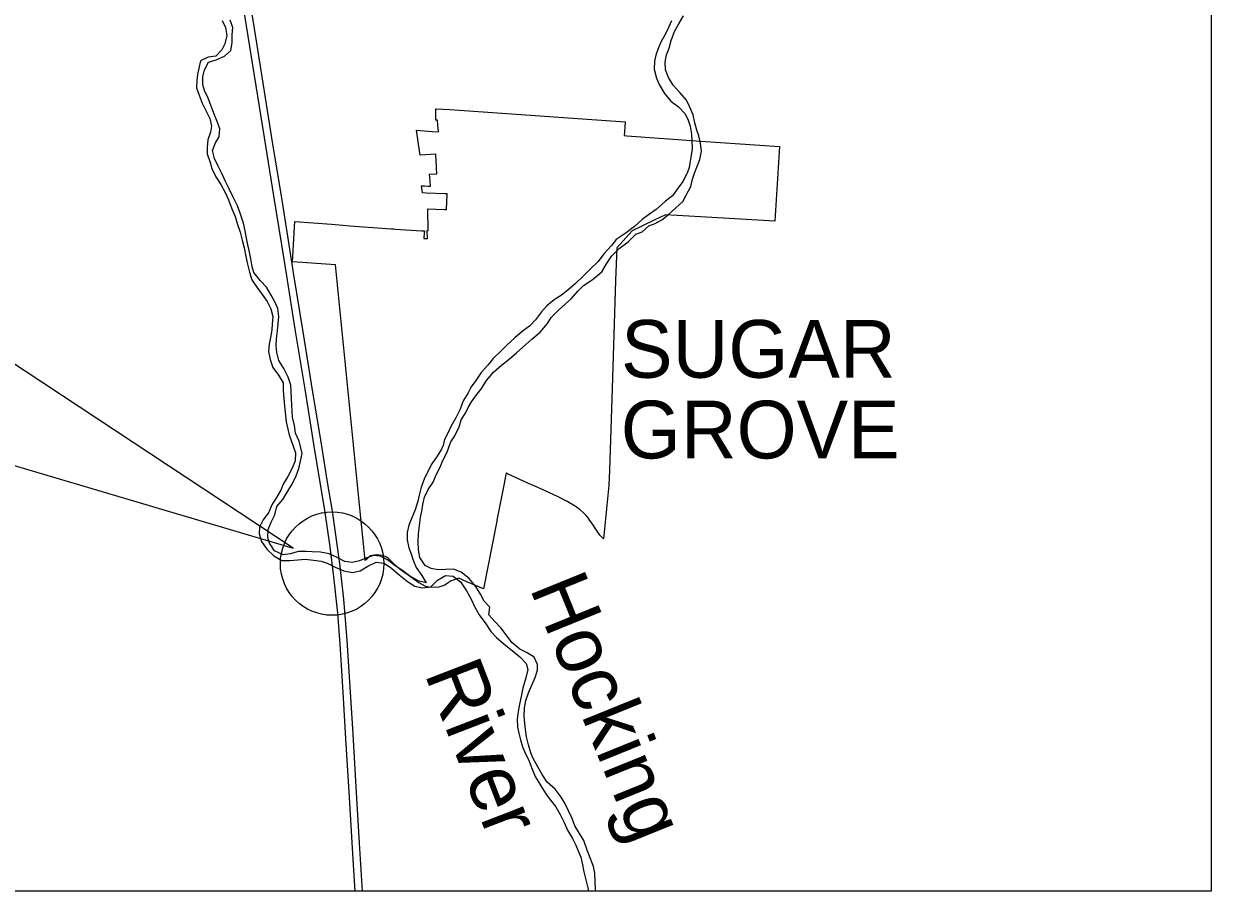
# Model space of a CAD drawing. Extents: x -51.9 to 34, y 0 to 23.3.
# Drawn here: x 9.235 to 12.658, y 11.236 to 13.737 of the extents above; entities that cross this region are included whole.
import ezdxf

# ---------------------------------------------------------------- set-up
doc = ezdxf.new("R2010")
doc.units = 0
for name, color, linetype in [('BR_P_Gen_Text', 7, 'Continuous'), ('Default', 7, 'Continuous'), ('GM_X_Corporation', 7, 'Continuous'), ('GM_X_Corporation_Text', 7, 'Continuous'), ('GM_X_Major_River', 7, 'Continuous'), ('GM_X_Major_River_Text', 7, 'Continuous'), ('GM_X_US_Route', 7, 'Continuous'), ('SH_Text', 7, 'Continuous')]:
    doc.layers.add(name, color=color, linetype=linetype)

msp = doc.modelspace()

# ---------------------------------------------------------------- linework, layer by layer
at = {"layer": 'BR_P_Gen_Text'}
msp.add_lwpolyline([(9.1878, 12.7694), (9.1878, 12.4691), (10.0115, 12.2252)], close=True, dxfattribs=at)
at = {"layer": 'Default'}
msp.add_circle((10.1237, 12.1807), 0.149, dxfattribs=at)
at = {"layer": 'GM_X_Corporation'}
msp.add_lwpolyline([(10.9674, 13.438), (10.966, 13.4149), (10.9733, 13.4144), (11.187, 13.3992), (11.414, 13.383), (11.3998, 13.1683), (11.1854, 13.1809), (11.1183, 13.1848), (11.0848, 13.1868), (11.0519, 13.1709), (10.9892, 13.1406), (10.9443, 13.0914), (10.9409, 12.9969), (10.9309, 12.6853), (10.9233, 12.4499), (10.9212, 12.4055), (10.9062, 12.2521), (10.8999, 12.2586), (10.8961, 12.2627), (10.8824, 12.283), (10.8755, 12.2934), (10.8728, 12.2975), (10.8726, 12.2977), (10.8651, 12.3082), (10.8649, 12.3086), (10.8578, 12.3172), (10.8567, 12.3185), (10.8566, 12.3187), (10.8563, 12.319), (10.8475, 12.3278), (10.8472, 12.3281), (10.8389, 12.3354), (10.8386, 12.3357), (10.8284, 12.3435), (10.828, 12.3438), (10.8279, 12.3438), (10.8263, 12.3449), (10.8222, 12.3475), (10.8149, 12.3521), (10.8146, 12.3523), (10.8108, 12.3545), (10.8035, 12.3586), (10.8003, 12.3604), (10.8, 12.3606), (10.7756, 12.3728), (10.7358, 12.3913), (10.7061, 12.4051), (10.699, 12.4083), (10.6292, 12.44), (10.6263, 12.4413), (10.6254, 12.4417), (10.6237, 12.433), (10.6196, 12.4121), (10.6149, 12.3875), (10.599, 12.3061), (10.5984, 12.3027), (10.5604, 12.1082), (10.512, 12.1278), (10.4894, 12.1383), (10.4666, 12.131), (10.4587, 12.1255), (10.4486, 12.1185), (10.4319, 12.1125), (10.4092, 12.1122), (10.3977, 12.1142), (10.3922, 12.1152), (10.3748, 12.1249), (10.3737, 12.1256), (10.3561, 12.1376), (10.3433, 12.147), (10.337, 12.1516), (10.3295, 12.1567), (10.3207, 12.1626), (10.2989, 12.1834), (10.2859, 12.1967), (10.2805, 12.1993), (10.2702, 12.2041), (10.2511, 12.2064), (10.2346, 12.2029), (10.2193, 12.1901), (10.2135, 12.2473), (10.2032, 12.3501), (10.1576, 12.802), (10.1334, 13.0424), (10.0095, 13.0509), (10.0166, 13.167), (10.1216, 13.1591), (10.1216, 13.1591), (10.1548, 13.1566), (10.1746, 13.1551), (10.2945, 13.1461), (10.2968, 13.1459), (10.3021, 13.1456), (10.3056, 13.1453), (10.3821, 13.1404), (10.3859, 13.1402), (10.39, 13.1399), (10.3883, 13.1216), (10.388, 13.1182), (10.3984, 13.1178), (10.3982, 13.1409), (10.401, 13.1408), (10.4001, 13.2037), (10.4224, 13.2027), (10.448, 13.2017), (10.4536, 13.2014), (10.4554, 13.245), (10.4555, 13.2467), (10.4531, 13.2468), (10.4498, 13.2469), (10.395, 13.2492), (10.3847, 13.2497), (10.3814, 13.2699), (10.3916, 13.2696), (10.401, 13.2694), (10.4078, 13.2692), (10.4065, 13.2847), (10.4049, 13.3034), (10.4253, 13.3048), (10.4247, 13.32), (10.4244, 13.3275), (10.4238, 13.34), (10.423, 13.3611), (10.3774, 13.3581), (10.373, 13.39), (10.3674, 13.4306), (10.4126, 13.427), (10.4304, 13.4256), (10.4288, 13.4447), (10.4277, 13.459), (10.4232, 13.4593), (10.4228, 13.4894), (10.4228, 13.4925), (10.4634, 13.4902), (10.9684, 13.4542)], close=True, dxfattribs=at)
at = {"layer": 'GM_X_Major_River'}
for points in [[(9.8067, 13.7471), (9.8167, 13.7265), (9.8201, 13.7038), (9.8142, 13.6798), (9.8063, 13.6618), (9.7884, 13.6437), (9.7665, 13.641), (9.7446, 13.6309), (9.74, 13.6089), (9.7361, 13.5909), (9.7334, 13.5735), (9.7328, 13.5522), (9.7402, 13.5315), (9.7496, 13.5082), (9.7596, 13.4876), (9.7716, 13.4643), (9.7757, 13.4423), (9.7731, 13.425), (9.7651, 13.403), (9.7632, 13.3816), (9.7633, 13.3623), (9.772, 13.3377), (9.7773, 13.3204), (9.7887, 13.2964), (9.8034, 13.2738), (9.8154, 13.2511), (9.8247, 13.2292), (9.8348, 13.2039), (9.8448, 13.1819), (9.8515, 13.1586), (9.8589, 13.136), (9.8649, 13.1133), (9.8703, 13.0913), (9.875, 13.0667), (9.8797, 13.044), (9.8858, 13.0207), (9.8925, 12.9988), (9.9065, 12.9775), (9.9225, 12.9569), (9.9365, 12.9362), (9.9472, 12.9149), (9.9526, 12.8936), (9.9513, 12.8716), (9.95, 12.855), (9.9461, 12.8329), (9.9428, 12.8136), (9.9409, 12.7923), (9.9456, 12.7689), (9.953, 12.7463), (9.9696, 12.7237), (9.9823, 12.7017), (9.9824, 12.6791), (9.9844, 12.6564), (9.9865, 12.6344), (9.9885, 12.6178), (9.9913, 12.5898), (9.996, 12.5685), (10, 12.5518), (10.0111, 12.5197)], [(10.0315, 12.5226), (10.0286, 12.5339), (10.0186, 12.5565), (10.0152, 12.5785), (10.0098, 12.6025), (10.0085, 12.6198), (10.0077, 12.6378), (10.0064, 12.6572), (10.0056, 12.6772), (10.0049, 12.6951), (9.9969, 12.7185), (9.9849, 12.7431), (9.9702, 12.7664), (9.9641, 12.7897), (9.9628, 12.8083), (9.9634, 12.829), (9.9666, 12.8517), (9.9686, 12.8717), (9.9705, 12.893), (9.9671, 12.9163), (9.9598, 12.9337), (9.9484, 12.9549), (9.9344, 12.9776), (9.9177, 12.9962), (9.8984, 13.0201), (9.8937, 13.0368), (9.8897, 13.0594), (9.8843, 13.0834), (9.8809, 13.1), (9.8775, 13.1194), (9.8728, 13.14), (9.8681, 13.1627), (9.8601, 13.1886), (9.8507, 13.2126), (9.8387, 13.2372), (9.8273, 13.2612), (9.8166, 13.2825), (9.8066, 13.3038), (9.7952, 13.3271), (9.7846, 13.3484), (9.7792, 13.3717), (9.7878, 13.3937), (9.7983, 13.4111), (9.8003, 13.4344), (9.7929, 13.4557), (9.7835, 13.477), (9.7748, 13.4997), (9.7661, 13.523), (9.7561, 13.5449), (9.7514, 13.5616), (9.7514, 13.5842), (9.7559, 13.6049), (9.7672, 13.627), (9.7891, 13.633), (9.8136, 13.6438), (9.8322, 13.6605), (9.8354, 13.6819), (9.8354, 13.7052), (9.838, 13.7265), (9.8299, 13.7478)], [(11.102, 13.7454), (11.0941, 13.728), (11.0849, 13.708), (11.071, 13.6846), (11.0624, 13.6633), (11.0571, 13.6466), (11.0532, 13.6292), (11.0526, 13.6066), (11.0593, 13.5806), (11.0667, 13.5619), (11.082, 13.5367), (11.1, 13.5141), (11.1226, 13.4981), (11.1413, 13.4775), (11.1506, 13.4589), (11.156, 13.4416), (11.1601, 13.4189), (11.1608, 13.4003), (11.1615, 13.3763), (11.1589, 13.3583), (11.1563, 13.3409), (11.153, 13.3229), (11.1471, 13.3062), (11.1345, 13.2829), (11.1213, 13.2641), (11.1048, 13.2414), (11.0849, 13.2254), (11.0577, 13.2019), (11.0358, 13.1865), (11.0173, 13.1725), (10.9954, 13.1531), (10.9715, 13.1343), (10.943, 13.1149), (10.9291, 13.0975), (10.9073, 13.0741), (10.8907, 13.0521), (10.8689, 13.0307), (10.8477, 13.0093), (10.8245, 12.9879), (10.8033, 12.9691), (10.7854, 12.9544), (10.7642, 12.9417), (10.743, 12.9236), (10.7277, 12.9069), (10.7105, 12.8835), (10.6933, 12.8654), (10.6721, 12.85), (10.6509, 12.832), (10.6277, 12.8105), (10.6111, 12.7938), (10.5879, 12.7718), (10.5727, 12.753), (10.5535, 12.7316), (10.5383, 12.7089), (10.5251, 12.6909), (10.5158, 12.6729), (10.5019, 12.6501), (10.4927, 12.6261), (10.4808, 12.6014), (10.4663, 12.576), (10.457, 12.5567), (10.4478, 12.5386), (10.4437, 12.5217), (10.4393, 12.5105)], [(10.4634, 12.5243), (10.4664, 12.5314), (10.4776, 12.5487), (10.4902, 12.5748), (10.4961, 12.5948), (10.5087, 12.6142), (10.5159, 12.6309), (10.5252, 12.6476), (10.5384, 12.6643), (10.555, 12.687), (10.5688, 12.7084), (10.5894, 12.7331), (10.6126, 12.7525), (10.6338, 12.7706), (10.6556, 12.788), (10.6821, 12.8127), (10.6994, 12.8281), (10.7232, 12.8482), (10.7451, 12.8729), (10.7557, 12.8903), (10.7769, 12.9117), (10.7954, 12.9291), (10.8126, 12.9445), (10.8318, 12.9659), (10.8484, 12.9826), (10.8736, 12.9987), (10.9014, 13.0221), (10.9147, 13.0455), (10.9299, 13.0682), (10.9517, 13.0896), (10.9769, 13.1083), (10.9994, 13.1304), (11.0174, 13.1378), (11.0366, 13.1545), (11.0552, 13.1613), (11.0744, 13.172), (11.0923, 13.1867), (11.1148, 13.2068), (11.1347, 13.2249), (11.1446, 13.2429), (11.1578, 13.2676), (11.1631, 13.2896), (11.169, 13.3063), (11.1749, 13.3237), (11.1835, 13.3463), (11.1888, 13.3697), (11.186, 13.3917), (11.1813, 13.4137), (11.1753, 13.4303), (11.1699, 13.4516), (11.1645, 13.4749), (11.1539, 13.4989), (11.1452, 13.5169), (11.1265, 13.5395), (11.1072, 13.5607), (11.0932, 13.582), (11.0845, 13.604), (11.0844, 13.6267), (11.0877, 13.648), (11.0956, 13.6667), (11.1008, 13.6894), (11.1107, 13.7148), (11.1233, 13.7368), (11.1365, 13.7602)], [(10.0111, 12.5197), (10.0186, 12.5001), (10.0172, 12.4774), (10.009, 12.4561), (9.9962, 12.4322), (9.9827, 12.4097), (9.9759, 12.3924), (9.9631, 12.3711), (9.9503, 12.3505), (9.9415, 12.3286), (9.9247, 12.3067), (9.9145, 12.2854), (9.9137, 12.2668), (9.9203, 12.2447), (9.9361, 12.2226), (9.956, 12.2031), (9.9786, 12.1896), (10.0019, 12.1895), (10.0246, 12.192), (10.0466, 12.1932), (10.0699, 12.191), (10.0919, 12.1875), (10.1098, 12.1821), (10.1331, 12.1706), (10.1577, 12.1597), (10.1823, 12.1549), (10.2043, 12.1601), (10.2271, 12.1732), (10.2512, 12.1844), (10.2738, 12.1816), (10.295, 12.1674), (10.3169, 12.1486), (10.3414, 12.1291), (10.362, 12.1156), (10.384, 12.1108), (10.408, 12.1133), (10.4281, 12.1331), (10.4509, 12.1463), (10.4729, 12.1442), (10.4941, 12.128), (10.5112, 12.1025), (10.5251, 12.0784), (10.5356, 12.055), (10.5474, 12.0329), (10.5666, 12.0075), (10.5818, 11.9854), (10.5977, 11.9679), (10.6202, 11.9484), (10.6427, 11.9303), (10.6646, 11.9121), (10.6831, 11.8926), (10.6877, 11.8753), (10.6822, 11.8513), (10.674, 11.822), (10.6685, 11.798), (10.6643, 11.7754), (10.6602, 11.7541), (10.6574, 11.7321), (10.6586, 11.7088), (10.6625, 11.6921), (10.667, 11.6727), (10.6729, 11.6526), (10.6814, 11.6319), (10.6906, 11.6138), (10.6991, 11.5931), (10.7089, 11.567), (10.7254, 11.5396), (10.7399, 11.5168), (10.7531, 11.4987), (10.769, 11.4793), (10.7815, 11.4572), (10.7927, 11.4338), (10.8026, 11.4123), (10.8164, 11.3882), (10.8263, 11.3688), (10.8335, 11.3521), (10.8407, 11.3341), (10.8446, 11.3167), (10.8497, 11.292), (10.8549, 11.2686), (10.8608, 11.2459), (10.863, 11.236)], [(10.4393, 12.5105), (10.4265, 12.4906), (10.411, 12.468), (10.3989, 12.4447), (10.3894, 12.4241), (10.3806, 12.4009), (10.3744, 12.3782), (10.371, 12.3609), (10.3635, 12.3356), (10.354, 12.313), (10.3452, 12.2911), (10.3404, 12.2705), (10.3402, 12.2491), (10.3448, 12.2264), (10.3513, 12.209), (10.3572, 12.191), (10.3657, 12.1696), (10.3822, 12.1468), (10.3954, 12.1254), (10.3708, 12.1309), (10.3482, 12.1444), (10.3263, 12.1605), (10.3057, 12.174), (10.2832, 12.1915), (10.2619, 12.2017), (10.2433, 12.2038), (10.2206, 12.1966), (10.2032, 12.1887), (10.1812, 12.1836), (10.1605, 12.187), (10.1386, 12.1979), (10.1153, 12.2093), (10.09, 12.2135), (10.066, 12.215), (10.0487, 12.2152), (10.0274, 12.216), (10.0027, 12.2088), (9.9827, 12.2063), (9.9581, 12.2178), (9.9429, 12.2392), (9.939, 12.2559), (9.9392, 12.2793), (9.948, 12.2999), (9.9588, 12.3211), (9.9649, 12.3451), (9.9817, 12.3657), (9.9966, 12.3896), (10.0094, 12.4121), (10.0202, 12.4334), (10.0277, 12.4554), (10.0325, 12.476), (10.0373, 12.4986), (10.0315, 12.5226)], [(10.8839, 11.236), (10.8834, 11.2424), (10.8822, 11.2631), (10.881, 11.2884), (10.8778, 11.3078), (10.868, 11.3319), (10.8595, 11.3546), (10.8497, 11.382), (10.8372, 11.4028), (10.8233, 11.4249), (10.8154, 11.4456), (10.8056, 11.4677), (10.7944, 11.4904), (10.7845, 11.5072), (10.7667, 11.53), (10.7435, 11.5501), (10.729, 11.5722), (10.7171, 11.595), (10.7039, 11.6184), (10.6967, 11.6351), (10.6902, 11.6585), (10.6844, 11.6812), (10.6812, 11.7026), (10.6793, 11.7193), (10.6774, 11.7413), (10.6789, 11.7646), (10.6824, 11.7859), (10.6899, 11.8079), (10.7, 11.8298), (10.7089, 11.8524), (10.7163, 11.8731), (10.7158, 11.8897), (10.7066, 11.9111), (10.686, 11.9239), (10.6648, 11.9341), (10.6416, 11.9536), (10.6257, 11.975), (10.6105, 11.9958), (10.5933, 12.014), (10.5754, 12.0327), (10.5782, 12.0547), (10.5624, 12.0728), (10.5512, 12.0929), (10.5386, 12.1144), (10.5188, 12.1378), (10.4963, 12.156), (10.4737, 12.1648), (10.451, 12.1636), (10.4297, 12.1631), (10.4097, 12.1666), (10.3917, 12.1754), (10.3766, 12.1982), (10.3727, 12.2209), (10.3722, 12.2436), (10.373, 12.2662), (10.3759, 12.2902), (10.3787, 12.3135), (10.3828, 12.3315), (10.3849, 12.3508), (10.3897, 12.3721), (10.4012, 12.3947), (10.4147, 12.4153), (10.4242, 12.4366), (10.435, 12.4592), (10.4431, 12.4784), (10.4546, 12.5004), (10.4634, 12.5243)]]:
    msp.add_lwpolyline(points, dxfattribs=at)
at = {"layer": 'GM_X_US_Route'}
for points in [[(9.8699, 13.9021), (9.8732, 13.8817), (9.8992, 13.7236), (9.9313, 13.5238), (9.9495, 13.4084), (9.9787, 13.2288), (9.9952, 13.1247), (10.012, 13.0195), (10.0397, 12.8486), (10.0675, 12.6751), (10.0912, 12.5317), (10.11, 12.4154), (10.124, 12.3317)], [(9.8492, 13.898), (9.8677, 13.7849), (9.8989, 13.5882), (9.9281, 13.4092), (9.9547, 13.2412), (9.9779, 13.0999), (9.992, 13.0102), (10.0163, 12.857), (10.0452, 12.6835), (10.0713, 12.5189), (10.1024, 12.328)], [(10.1024, 12.328), (10.1172, 12.2289), (10.1279, 12.1427), (10.1389, 12.0375), (10.1462, 11.9487), (10.1511, 11.8718), (10.1557, 11.7932), (10.1626, 11.6761), (10.173, 11.5063), (10.1849, 11.3123), (10.1895, 11.236)], [(10.124, 12.3317), (10.1456, 12.1809), (10.1566, 12.078), (10.1667, 11.96), (10.1719, 11.8698), (10.1823, 11.705), (10.1924, 11.5373), (10.2023, 11.3745), (10.2108, 11.236)]]:
    msp.add_lwpolyline(points, dxfattribs=at)
at = {"layer": 'SH_Text'}
msp.add_lwpolyline([(2.2024, 20.8014), (12.6582, 20.8014), (12.6582, 11.236), (2.2024, 11.236)], close=True, dxfattribs=at)

# ---------------------------------------------------------------- texts
at = {"layer": 'GM_X_Corporation_Text'}
for s, p in [('SUGAR', (10.9568, 12.7166)), ('GROVE', (10.956, 12.484))]:
    msp.add_text(s, height=0.16646, rotation=0, dxfattribs=at).set_placement(p)
at = {"layer": 'GM_X_Major_River_Text'}
for s, height, rotation, p in [('Hocking', 0.16647, 292.0997, (10.6921, 12.1109)), ('River', 0.16645, 291.1244, (10.389, 11.8642))]:
    msp.add_text(s, height=height, rotation=rotation, dxfattribs=at).set_placement(p)

doc.saveas('drawing.dxf')
